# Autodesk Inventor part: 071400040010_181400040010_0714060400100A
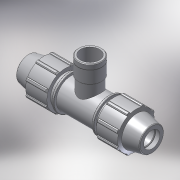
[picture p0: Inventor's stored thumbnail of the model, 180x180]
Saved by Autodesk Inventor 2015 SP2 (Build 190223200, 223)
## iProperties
Created: 2017-02
Part Number: 071400040010_181400040010_0714060400100A
Material: PVC-Piping
Description: PLASSON TEE WITH THREADED FEMALE OFFTAKE 40-1"-40
Document SubType Name: Modeling
Designer: KIM
Mass: 92.6774 g
Surface Area: 199.44 cm^2
Volume: 66.1981 cm^3
Density: 1.4 g/cm^3
Appearance: Smooth - White
Author: KIM
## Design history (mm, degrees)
derived "07140.ipt"
feature "Solid1::07140.ipt"
feature "Solid2::07140.ipt"
tag "TaggingFeature1"
body "Solid1"
other parameters: "d4" = 8.45833, "d5" = 24.36, "d7" = 82, "d11" = 3.38333, "d13" = 120 deg, "d15" = 12 deg, "d16" = 71.34, "d18" = 2, "d19" = 35 deg, "d20" = 17.5 deg, "d21" = 76.26, "d23" = 0, "d25" = 360 deg, "d27" = 1.64, "d33" = 0.8, "d42" = 36.54, "d43" = 2.46, "d46" = 1.2, "d68" = 6.09, "d72" = 61, "d76" = 30.291, "d80" = 0.90873, "d91" = 61.5, "d93" = 84, "d95" = 36, "d112" = 21, "d115" = 37.86375, "d116" = 135 deg, "d117" = 34.83465, "d118" = 203, "d119" = 36, "d121" = 0, "d122" = 25.2, "d124" = 0, "d128" = 0, "d129" = 4, "d130" = 6.3, "d131" = 0.3, "d132" = 0.3, "d133" = 37.86375, "E_" = 82, "A_" = 61, "l_" = 84, "l_2" = 21, "Rp_" = 30.291, "H_" = 203
